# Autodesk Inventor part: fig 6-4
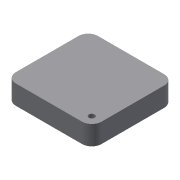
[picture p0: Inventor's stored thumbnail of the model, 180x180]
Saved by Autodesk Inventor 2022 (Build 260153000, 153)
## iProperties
Created: 2004-05
Part Number: fig 6-4
Document SubType Name: Modeling
Designer: CADCIM Technologies
Manufacturer: Standard
Standards Organization: Custom
Density: 1 g/cm^3
Material: Generic
Appearance: Default
Author: CADCIM Technologies
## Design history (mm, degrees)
sketch "Sketch1"
  geometry: L1 (0, 0)-(44.293, 0); L2 (44.293, 0)-(44.293, 42.442); L3 (44.293, 42.442)-(0, 42.442); L4 (0, 42.442)-(0, 0)
  constraints: 8 end point, 2 parallel, 1 horizontal, 1 perpendicular
extrude "Extrusion1" new body sketch "Sketch1" distance "d0" = 10; taper "d1" = 0 deg
fillet "Fillet1" dims "d2" = 5
sketch "Sketch2"
  geometry: 1 further point
sketch "Sketch3"
  geometry: L1 (5, 42.442)-(39.293, 42.442) reference; L2 (0, 5)-(0, 37.442) reference; L3 (39.293, 0)-(5, 0) reference; L4 (44.293, 37.442)-(44.293, 5) reference; A1 r 5 centre (39.293, 37.442) between (44.293, 37.442) and (39.293, 42.442) reference; A2 r 5 centre (5, 37.442) between (5, 42.442) and (0, 37.442) reference; A3 r 5 centre (5, 5) between (0, 5) and (5, 0) reference; A4 r 5 centre (39.293, 5) between (39.293, 0) and (44.293, 5) reference; 1 further point
hole "Hole2" diameter "d15" = 3; stored, may be unused: countersink angle "d19" = 90 deg, drill point angle "d21" = 118 deg; dims "d13" = 10, "d14" = 10, "d16" = 6, "d17" = 4, "d18" = 2, "d20" = 8
body "Solid1"
